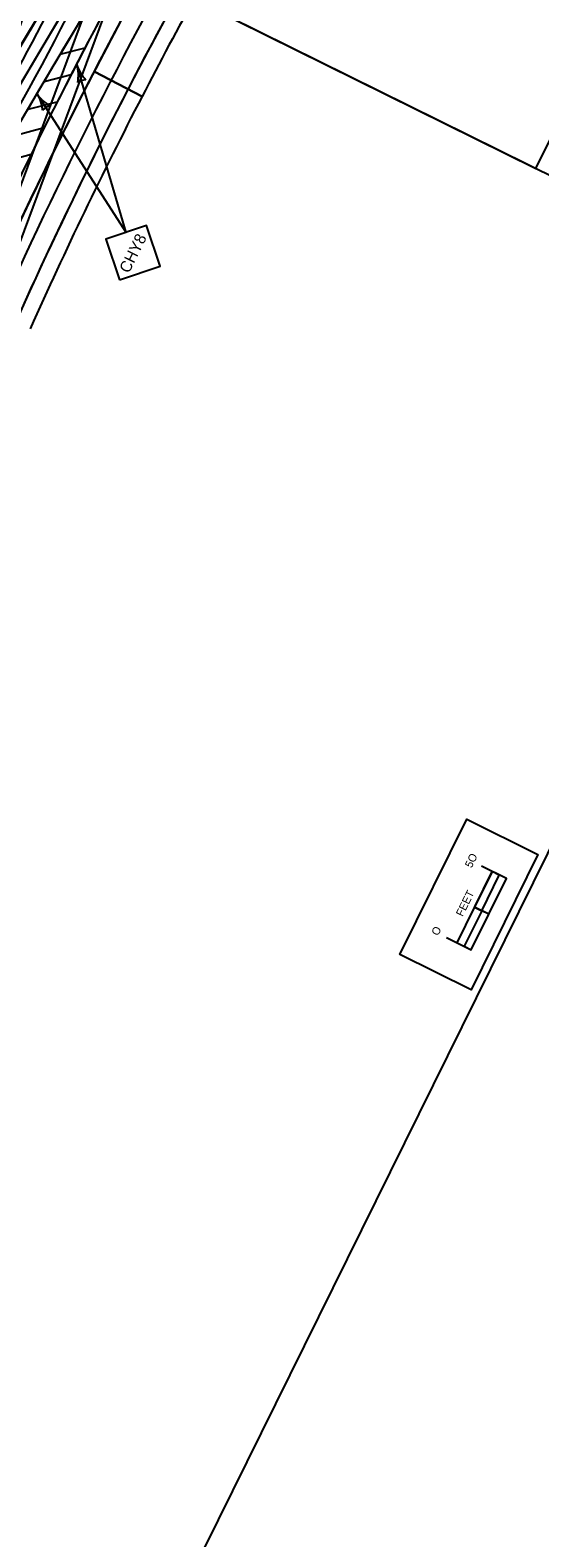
# Model space of a CAD drawing. Extents: x 14097936 to 14128734, y 8632000 to 8683104.
# Drawn here: x 14118997 to 14119318, y 8667745 to 8668694 of the extents above; entities that cross this region are included whole.
import ezdxf

# ---------------------------------------------------------------- set-up
doc = ezdxf.new("R2010")
doc.units = 0
for name, color, linetype in [('dsn_stg_shd_prev', 7, 'Continuous'), ('dsnCellsScaleBlock', 7, 'Continuous'), ('dsnNonPlotable', 7, 'Continuous'), ('dsnPaintExistingChannelizingLaneWhite', 7, 'Continuous'), ('dsnPaintPlaceBrokenLaneWhite', 7, 'Continuous'), ('dsnPaintPlaceChannelizingLaneWhite', 7, 'Continuous'), ('dsnPaintPlaceChannelizingLaneYellow', 7, 'Continuous'), ('dsnPaintPlaceEdgeLineRightWhite', 7, 'Continuous'), ('dsnPaintPlaceLaneLineWhite', 7, 'Continuous'), ('dsnShadingPaved', 7, 'Continuous'), ('dsnStdLabel', 7, 'Continuous'), ('dsnStgShadingPrevPav', 7, 'Continuous'), ('dsnStgShadingPropPav', 7, 'Continuous'), ('dsnTapeRemoveChannelizingLaneWhite', 7, 'Continuous'), ('dsnTapeRemoveChannelizingLaneYellow', 7, 'Continuous')]:
    doc.layers.add(name, color=color, linetype=linetype)

msp = doc.modelspace()

# ---------------------------------------------------------------- linework, layer by layer
at = {"layer": 'dsn_stg_shd_prev'}
for centre, radius, start, end in [((14123732.59, 8665873.82), 5512, 146.41866, 157.1633), ((14123732.59, 8665873.82), 5512, 146.50213, 150.36196), ((14121591.75, 8667345.11), 2876.96, 147.23629, 155.33788)]:
    msp.add_arc(centre, radius, start, end, dxfattribs=at)
at = {"layer": 'dsnCellsScaleBlock'}
msp.add_line((14119285.61, 8668137.89), (14119276.65, 8668142.32), dxfattribs=at)
msp.add_line((14119285.61, 8668137.89), (14119276.65, 8668142.32), dxfattribs=at)
for points in [[(14119229.6, 8668112.59), (14119271.71, 8668197.75), (14119316.53, 8668175.59), (14119274.42, 8668090.43)], [(14119274.42, 8668090.43), (14119229.6, 8668112.59), (14119271.71, 8668197.75), (14119316.53, 8668175.59)], [(14119281.1, 8668140.12), (14119292.18, 8668162.53), (14119287.73, 8668164.73), (14119276.65, 8668142.32)], [(14119274.53, 8668115.48), (14119285.61, 8668137.89), (14119281.1, 8668140.12), (14119270.02, 8668117.71)]]:
    msp.add_lwpolyline(points, close=True, dxfattribs=at)
for points in [[(14119258.85, 8668123.23), (14119274.53, 8668115.48), (14119296.69, 8668160.3), (14119281.01, 8668168.05)], [(14119265.57, 8668119.91), (14119287.73, 8668164.73)]]:
    msp.add_lwpolyline(points, dxfattribs=at)
at = {"layer": 'dsnNonPlotable'}
for points in [[(14118631.64, 8668945.1), (14119326.37, 8670350.23), (14120231.75, 8669902.59), (14119537.02, 8668497.46)], [(14119315.27, 8668607.09), (14120010, 8670012.23), (14119557.31, 8670236.05), (14118862.58, 8668830.91)], [(14118047.21, 8667875.87), (14118741.94, 8669281.01), (14119647.32, 8668833.36), (14118952.59, 8667428.23)]]:
    msp.add_lwpolyline(points, close=True, dxfattribs=at)
at = {"layer": 'dsnPaintExistingChannelizingLaneWhite'}
msp.add_arc((14118409.81, 8668902.17), 616, 336.56541, 343.63038, dxfattribs=at)
at = {"layer": 'dsnPaintPlaceBrokenLaneWhite'}
for centre, radius, start in [((14123732.96, 8665874.38), 5500, 147.11705), ((14121592.11, 8667345.68), 2864.95, 151.16499)]:
    msp.add_arc(centre, radius, start, 157.1633, dxfattribs=at)
at = {"layer": 'dsnPaintPlaceChannelizingLaneWhite'}
msp.add_arc((14123732.96, 8665874.38), 5512, 148.26304, 149.67774, dxfattribs=at)
at = {"layer": 'dsnPaintPlaceChannelizingLaneYellow'}
for p, q in [((14119015.87, 8668679.24), (14119031.44, 8668683.2)), ((14119005.68, 8668662.04), (14119022.76, 8668666.44)), ((14118995.73, 8668644.44), (14119013.98, 8668649.22)), ((14118985.49, 8668627.51), (14119005.79, 8668632.9)), ((14118975.49, 8668610.19), (14118997.51, 8668616.13))]:
    msp.add_line(p, q, dxfattribs=at)
for centre, radius, start, end in [((14123748.96, 8665864.73), 5506.68, 148.38653, 150.66501), ((14121592.11, 8667345.68), 2888.95, 150.97391, 155.3184)]:
    msp.add_arc(centre, radius, start, end, dxfattribs=at)
at = {"layer": 'dsnPaintPlaceEdgeLineRightWhite'}
msp.add_arc((14121592.11, 8667345.68), 2852.95, 151.16499, 157.1633, dxfattribs=at)
at = {"layer": 'dsnPaintPlaceLaneLineWhite'}
msp.add_arc((14121592.11, 8667345.68), 2876.95, 150.94619, 156.23387, dxfattribs=at)
at = {"layer": 'dsnShadingPaved'}
for centre, radius, start, end in [((14123732.96, 8665874.38), 5500, 145.2497, 157.1633), ((14123732.96, 8665874.38), 5488, 145.2497, 157.1633), ((14123732.96, 8665874.38), 5500, 146.42378, 157.1633), ((14121592.11, 8667345.68), 2876.95, 147.15737, 157.1633), ((14123655.03, 8665915.77), 5424.12, 146.80648, 157.24675), ((14121592.11, 8667345.68), 2852.95, 147.15737, 157.1633), ((14121592.11, 8667345.68), 2876.95, 149.16283, 157.1633), ((14121592.11, 8667345.68), 2888.95, 150.97391, 156.23389), ((14118409.81, 8668902.17), 616, 336.78135, 343.63038)]:
    msp.add_arc(centre, radius, start, end, dxfattribs=at)
at = {"layer": 'dsnStdLabel'}
for q in [(14119026.36, 8668672.52), (14119001.15, 8668654.34)]:
    msp.add_line((14119057.38, 8668567), q, dxfattribs=at)
msp.add_lwpolyline([(14119053.24, 8668537.09), (14119078.82, 8668545.75), (14119070.16, 8668571.32), (14119044.59, 8668562.67)], close=True, dxfattribs=at)
for centre, radius, start, end in [((14119004.34, 8668666.04), 22.95, 348.30998, 16.38128), ((14119048.38, 8668678.99), 22.95, 196.38113, 224.45239), ((14119031.78, 8668654.06), 8.86, 88.64696, 124.11541), ((14118981.86, 8668641.92), 22.95, 4.69778, 32.76909), ((14119020.45, 8668666.76), 22.95, 212.76894, 240.8402), ((14119011.57, 8668638.16), 8.86, 105.03477, 140.50321)]:
    msp.add_arc(centre, radius, start, end, dxfattribs=at)
at = {"layer": 'dsnStgShadingPrevPav'}
for centre, radius, start, end in [((14123732.96, 8665874.38), 5512, 146.41866, 157.1633), ((14121592.12, 8667345.67), 2876.96, 147.23629, 155.33788)]:
    msp.add_arc(centre, radius, start, end, dxfattribs=at)
at = {"layer": 'dsnStgShadingPropPav'}
for p, q in [((14119067.32, 8668652.5), (14119037.13, 8668668.13)), ((14119037.13, 8668668.13), (14119067.32, 8668652.5))]:
    msp.add_line(p, q, dxfattribs=at)
for centre, radius, start, end in [((14123732.59, 8665873.82), 5512, 146.50213, 150.36196), ((14121592.11, 8667345.68), 2876.95, 151.16499, 152.63404), ((14121592.11, 8667345.68), 2842.95, 151.16499, 152.63404), ((14121592.11, 8667345.68), 2876.95, 152.63404, 155.90343), ((14121592.11, 8667345.68), 2842.95, 152.63404, 155.90343)]:
    msp.add_arc(centre, radius, start, end, dxfattribs=at)
at = {"layer": 'dsnTapeRemoveChannelizingLaneWhite'}
msp.add_line((14118983.04, 8668540.5), (14119108.11, 8668877.26), dxfattribs=at)
msp.add_arc((14117682.33, 8669381.12), 1488, 329.20119, 337.13903, dxfattribs=at)
at = {"layer": 'dsnTapeRemoveChannelizingLaneYellow'}
msp.add_line((14118971.78, 8668544.68), (14119088.49, 8668858.92), dxfattribs=at)
msp.add_arc((14117682.32, 8669381.12), 1500, 329.20119, 339.62671, dxfattribs=at)

# ---------------------------------------------------------------- texts
at = {"layer": 'dsnCellsScaleBlock'}
for s, p in [('5O', (14119274.72, 8668166.62)), ('FEET', (14119269.08, 8668136.05)), ('O', (14119253.64, 8668123.99))]:
    msp.add_text(s, height=5, rotation=63.69117, dxfattribs=at).set_placement(p)
at = {"layer": 'dsnStdLabel'}
msp.add_text('CHY8', height=7.2, rotation=63.69117, dxfattribs=at).set_placement((14119059.08, 8668540.78))

doc.saveas('drawing.dxf')
